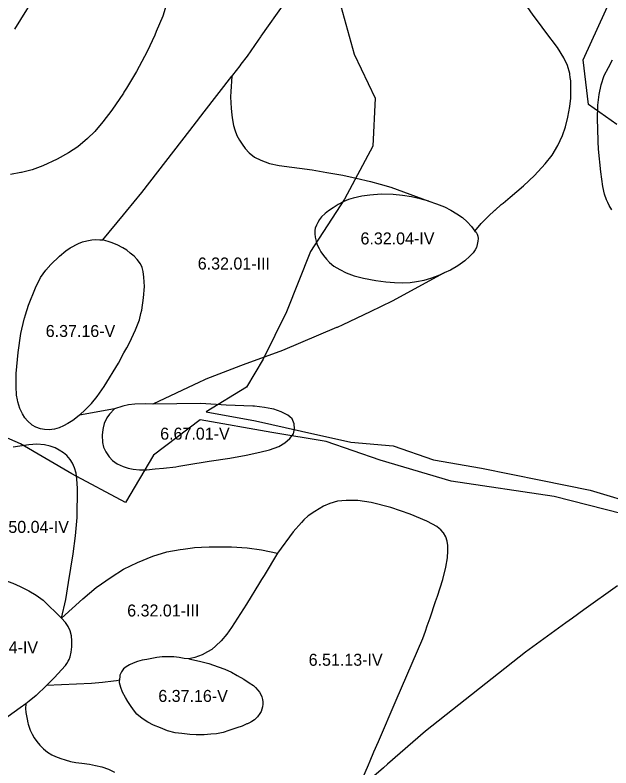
# Model space of a CAD drawing. Extents: x -555156 to -540209, y -1046851 to -1035695.
# Drawn here: x -543996 to -543499, y -1039781 to -1039153 of the extents above; entities that cross this region are included whole.
import ezdxf

# ---------------------------------------------------------------- set-up
doc = ezdxf.new("R2010")
doc.units = 0
for name, color, linetype in [('Vrstva 27', 7, 'Continuous'), ('Vrstva 28', 7, 'Continuous'), ('Vrstva 29', 7, 'Continuous')]:
    doc.layers.add(name, color=color, linetype=linetype)

msp = doc.modelspace()

# ---------------------------------------------------------------- linework, layer by layer
at = {"layer": 'Vrstva 28'}
for points in [[(-543869.35, -1039142.47), (-543873.01, -1039154.5), (-543875.74, -1039160.87), (-543878.5, -1039167.32), (-543879.8, -1039170.14), (-543886.08, -1039183.79), (-543894.97, -1039200.53), (-543903.32, -1039214.33), (-543905.42, -1039217.79), (-543905.88, -1039218.46), (-543915.62, -1039232.7), (-543923.04, -1039242.44), (-543929.76, -1039250.51), (-543935.89, -1039256.34), (-543943.95, -1039263.22), (-543951.57, -1039268.45), (-543961.13, -1039273.53), (-543973.08, -1039279.06), (-543982.04, -1039282.5), (-543985.24, -1039283.25), (-543991.05, -1039284.61), (-543991.6, -1039284.74), (-544000.11, -1039286.38)], [(-543771.41, -1039143.35), (-543791.13, -1039171), (-543791.65, -1039171.76), (-543793.42, -1039174.37), (-543802.57, -1039187.84), (-543807.8, -1039194.41), (-543808.8, -1039195.72), (-543814.8, -1039203.62), (-543815.42, -1039204.43)], [(-543612.61, -1039333.64), (-543607.39, -1039327.22), (-543601.71, -1039321.54), (-543596.11, -1039316.23), (-543595.88, -1039316.01), (-543590.66, -1039311.37), (-543589.15, -1039310.17), (-543583.19, -1039305.4), (-543572, -1039295.78), (-543563.03, -1039287.27), (-543554.07, -1039277.55), (-543548.25, -1039270.38), (-543543.47, -1039262.31), (-543539.58, -1039253.79), (-543537.19, -1039246.62), (-543535.1, -1039238.69), (-543533.54, -1039229.62), (-543532.65, -1039222.74), (-543532.5, -1039216.16), (-543532.65, -1039208.24), (-543533.05, -1039205.49), (-543533.46, -1039202.66), (-543533.54, -1039202.12), (-543535.48, -1039195.54), (-543538.47, -1039189.11), (-543543.73, -1039180.59), (-543553.4, -1039167.77), (-543559.73, -1039159.41), (-543564.07, -1039153.68), (-543568.98, -1039146.3)], [(-543498.55, -1039315.99), (-543500.51, -1039312.23), (-543501.81, -1039309.67), (-543502.9, -1039307.53), (-543504.44, -1039302.66), (-543505.94, -1039296.34), (-543507.59, -1039284.23), (-543509.53, -1039265.4), (-543509.73, -1039258.78), (-543510.05, -1039248.08), (-543510.28, -1039240.44), (-543510.11, -1039228.65), (-543509.06, -1039219.84), (-543507.27, -1039211.77), (-543504.73, -1039203.99), (-543501.29, -1039197.12), (-543497.86, -1039190.84)], [(-543923.2, -1039340.97), (-543905.93, -1039320.1), (-543903.43, -1039317.08), (-543890.52, -1039301.47), (-543850.45, -1039249.71), (-543847.58, -1039246), (-543838.42, -1039234.17), (-543815.42, -1039204.43)], [(-543815.42, -1039204.43), (-543816.37, -1039217.23), (-543816.45, -1039221.75), (-543816.28, -1039226.79), (-543816.02, -1039231.06), (-543815.51, -1039236.95), (-543814.91, -1039240.88), (-543814.06, -1039245.41), (-543813.04, -1039249.08), (-543811.16, -1039253.95), (-543809.11, -1039257.71), (-543806.72, -1039261.12), (-543804.33, -1039264.62), (-543801.09, -1039268.34), (-543796.56, -1039271.92), (-543791.36, -1039274.4), (-543783.93, -1039277.13), (-543775.91, -1039279.01), (-543748.33, -1039282.41), (-543736.23, -1039284.65), (-543722.79, -1039287.05), (-543711.77, -1039289.54), (-543699.63, -1039292.28), (-543691.81, -1039294.51), (-543682.9, -1039297.06)], [(-543682.9, -1039297.06), (-543651.2, -1039308.7)], [(-543651.2, -1039308.7), (-543658.29, -1039306.66), (-543665.54, -1039305.03), (-543672.97, -1039303.84), (-543680.82, -1039303.15), (-543690.72, -1039302.9), (-543700.28, -1039303.58), (-543706.94, -1039304.52), (-543714.11, -1039306.06), (-543718.21, -1039307.34), (-543721.97, -1039308.97), (-543726.83, -1039311.44), (-543730.93, -1039314.09), (-543734.69, -1039316.65), (-543737.5, -1039318.87), (-543740.57, -1039321.78), (-543742.28, -1039324), (-543743.73, -1039326.3), (-543744.84, -1039328.52), (-543745.95, -1039331), (-543746.29, -1039333.13), (-543746.29, -1039335.78), (-543745.95, -1039338.6), (-543745.18, -1039342.1), (-543744.16, -1039345.01), (-543742.62, -1039348.08), (-543741.09, -1039350.81), (-543739.04, -1039353.89), (-543736.56, -1039356.88), (-543733.83, -1039359.86), (-543730.35, -1039362.79), (-543725.31, -1039365.61), (-543720.19, -1039368.26), (-543713.28, -1039370.82), (-543705.51, -1039372.78), (-543695.44, -1039374.66), (-543686.99, -1039375.94), (-543679.73, -1039376.45), (-543672.99, -1039376.62), (-543666.59, -1039376.45)], [(-543651.2, -1039308.7), (-543644.63, -1039310.84), (-543638.15, -1039313.32), (-543632.68, -1039316.22), (-543627.65, -1039319.29), (-543623.12, -1039322.37), (-543619.11, -1039325.87), (-543615.61, -1039329.8), (-543612.61, -1039333.64)], [(-543612.61, -1039333.64), (-543611.73, -1039334.55), (-543610.75, -1039336.26), (-543610.31, -1039337.72), (-543610.07, -1039339.62), (-543610.16, -1039342.02), (-543610.65, -1039344.65), (-543611.43, -1039347.38), (-543612.36, -1039349.24), (-543614.05, -1039351.75), (-543616.79, -1039354.4), (-543620.97, -1039358.24), (-543627.03, -1039362.51), (-543633, -1039366.1), (-543638.21, -1039368.49)], [(-543963.42, -1039498.58), (-543967.78, -1039499.26), (-543971.62, -1039499.01), (-543975.2, -1039498.41), (-543979.04, -1039497.04), (-543981.94, -1039495.25), (-543985.96, -1039491.83), (-543988.09, -1039489.19), (-543990.22, -1039485.86), (-543992.19, -1039481.5), (-543993.98, -1039476.03), (-543994.31, -1039474.15), (-543995, -1039470.23), (-543995.43, -1039463.14), (-543995.26, -1039452.38), (-543993.79, -1039434.72), (-543991.4, -1039418.88), (-543988.82, -1039407.11), (-543988.71, -1039406.62), (-543988.54, -1039406.09), (-543987.67, -1039403.37), (-543985.12, -1039395.41), (-543979.37, -1039380.82), (-543978.91, -1039379.93), (-543975.89, -1039374.13), (-543974.97, -1039372.37), (-543970.7, -1039366.22), (-543966.52, -1039361.43), (-543959.18, -1039354.35), (-543954.06, -1039350.15), (-543950.35, -1039347.51), (-543943.28, -1039343.9), (-543940.01, -1039342.63), (-543936.5, -1039341.56), (-543932.31, -1039340.88), (-543929.14, -1039340.59), (-543925.58, -1039340.73), (-543923.2, -1039340.97)], [(-543942.43, -1039486.97), (-543937.48, -1039482.44), (-543932.61, -1039477.32), (-543927.74, -1039471.34), (-543922.08, -1039463.18), (-543909.98, -1039443.6), (-543905.42, -1039435.14), (-543903.07, -1039430.79), (-543900.87, -1039426.71), (-543895.71, -1039415.77), (-543892.58, -1039407.55), (-543891.24, -1039402.4), (-543890.48, -1039399.48), (-543889.14, -1039389.16), (-543888.39, -1039379.9), (-543888.78, -1039371.91), (-543889.46, -1039367.39), (-543890.23, -1039363.89), (-543891.76, -1039360.9), (-543894.5, -1039357.31), (-543896.97, -1039354.49), (-543900.21, -1039351.84), (-543903.12, -1039349.54), (-543906.45, -1039347.4), (-543910.97, -1039345.1), (-543916.09, -1039343.05), (-543923.2, -1039340.97)], [(-543638.21, -1039368.49), (-543681.7, -1039391.96), (-543699.92, -1039400.93), (-543722.83, -1039411.66), (-543727.6, -1039413.89), (-543728, -1039414.08), (-543773.2, -1039433.2), (-543805.87, -1039444.97), (-543808.21, -1039445.88), (-543837.19, -1039457.15), (-543838.81, -1039457.78), (-543842.48, -1039459.5), (-543881.41, -1039477.78)], [(-543666.59, -1039376.45), (-543661.3, -1039375.68), (-543654.9, -1039374.4), (-543649.39, -1039372.76), (-543643.33, -1039370.62), (-543638.21, -1039368.49)], [(-543913.33, -1039481.79), (-543917.51, -1039486.21), (-543919.81, -1039489.37), (-543921.86, -1039493.98), (-543922.76, -1039497.59), (-543923.14, -1039499.1), (-543923.74, -1039503.71), (-543923.31, -1039509.69), (-543922.37, -1039513.62), (-543920.58, -1039517.55), (-543917.76, -1039521.73), (-543914.86, -1039524.81), (-543911.1, -1039527.71), (-543906.07, -1039529.85), (-543901.97, -1039531.21), (-543897.87, -1039532.07), (-543892.41, -1039532.58), (-543886.61, -1039532.58), (-543879.27, -1039531.9), (-543872.4, -1039531.17), (-543862.07, -1039529.97), (-543859.62, -1039529.57), (-543852.98, -1039528.5), (-543834.31, -1039525.36), (-543816.98, -1039522.82), (-543803.39, -1039520.28), (-543792.19, -1039517.74), (-543783.97, -1039515.95), (-543776.35, -1039513.26), (-543771.12, -1039510.12), (-543767.09, -1039506.53), (-543763.95, -1039502.5), (-543763.06, -1039498.31), (-543763.36, -1039494.28), (-543765, -1039490.09), (-543767.01, -1039488.48), (-543768.73, -1039487.1), (-543774.41, -1039484.26), (-543780.53, -1039482.02), (-543782.03, -1039481.73), (-543788.15, -1039480.53), (-543796.62, -1039479.66), (-543798.01, -1039479.52), (-543820.23, -1039478.73), (-543841.4, -1039477.43)], [(-543881.41, -1039477.78), (-543887.55, -1039477.7), (-543896.26, -1039477.87), (-543901.72, -1039478.29), (-543906.33, -1039479.49), (-543913.33, -1039481.79)], [(-543841.4, -1039477.43), (-543881.41, -1039477.78)], [(-543913.33, -1039481.79), (-543942.43, -1039486.97)], [(-543942.43, -1039486.97), (-543944.08, -1039488.31), (-543947.97, -1039491.49), (-543952.16, -1039493.88), (-543955.74, -1039496.02), (-543959.41, -1039497.47), (-543963.42, -1039498.58)], [(-543953.85, -1039640.58), (-543951.61, -1039626.54), (-543947.69, -1039602.74), (-543945.9, -1039587.49), (-543944.56, -1039572.25), (-543944.41, -1039562.81), (-543944.33, -1039557.66), (-543944.26, -1039553.05), (-543944.18, -1039548.04), (-543944.7, -1039540.01), (-543945.29, -1039535.4), (-543946.57, -1039530.87), (-543948.28, -1039527.03), (-543950.24, -1039523.87), (-543953.06, -1039520.71), (-543955.96, -1039518.4), (-543959.46, -1039516.1), (-543962.96, -1039514.3), (-543967.06, -1039512.77), (-543971.84, -1039511.83), (-543978.07, -1039511.32), (-543984.9, -1039511.66), (-543997.85, -1039513.61)], [(-543678.31, -1039724.54), (-543656.09, -1039673.28), (-543654.99, -1039670.09), (-543653.92, -1039667), (-543652.46, -1039662.78), (-543650.11, -1039655.96), (-543645.42, -1039642.38), (-543643.88, -1039637.93), (-543639.4, -1039624.03), (-543637.01, -1039613.72), (-543635.63, -1039605.93), (-543635.25, -1039600.06), (-543635.21, -1039599.36), (-543635.21, -1039595.6), (-543635.72, -1039592.18), (-543637, -1039588.34), (-543638.88, -1039585.1), (-543639.19, -1039584.77), (-543641.18, -1039582.62), (-543642.46, -1039581.55), (-543644.34, -1039579.97), (-543647.92, -1039577.84), (-543652.67, -1039575.43), (-543666.56, -1039569.61), (-543682.84, -1039563.93), (-543699.27, -1039559.89), (-543710.33, -1039558.1), (-543720.19, -1039558.1), (-543727.21, -1039558.85), (-543733.63, -1039560.79), (-543738.86, -1039563.03), (-543746.33, -1039567.21), (-543751.7, -1039570.95), (-543755.25, -1039574.41), (-543757.38, -1039576.48), (-543764.25, -1039584.25), (-543777.31, -1039602.08)], [(-543957.44, -1039656.13), (-543939.67, -1039640.19), (-543928.62, -1039630.62), (-543916.22, -1039622.1), (-543905.77, -1039615.53), (-543894.12, -1039609.85), (-543881.42, -1039604.47), (-543869.77, -1039601.03), (-543858.42, -1039598.94), (-543855.98, -1039598.63), (-543848.17, -1039597.65), (-543846.47, -1039597.44), (-543840.65, -1039597.16), (-543834.22, -1039596.85), (-543815.85, -1039596.85), (-543802.55, -1039597.74), (-543790.75, -1039599.24), (-543777.31, -1039602.08)], [(-543777.31, -1039602.08), (-543788.59, -1039620.7), (-543790.6, -1039624.02), (-543792.35, -1039626.92), (-543803.08, -1039644.66), (-543815.62, -1039664.01), (-543819.69, -1039669.62), (-543824.47, -1039675.15), (-543828.66, -1039679.33), (-543832.09, -1039682.32), (-543835.83, -1039684.41), (-543840.31, -1039686.95)], [(-544052.34, -1039612.26), (-544044.67, -1039614.28), (-544035.71, -1039616.37), (-544024.36, -1039619.21), (-544014.95, -1039621.6), (-544005.09, -1039624.59), (-543998.22, -1039627.13), (-543991.94, -1039629.97), (-543984.92, -1039633.56), (-543978.8, -1039637.15), (-543972.97, -1039641.33), (-543957.44, -1039656.13)], [(-543493.68, -1039629.17), (-543521.66, -1039649.33), (-543531.19, -1039656.2), (-543536.67, -1039660.15), (-543570.53, -1039684.55), (-543653.79, -1039750.46), (-543685.64, -1039778.03), (-543689.02, -1039780.95), (-543710.72, -1039799.73)], [(-543957.44, -1039656.13), (-543953.85, -1039640.58)], [(-543970.12, -1039712.44), (-543963.29, -1039705.78), (-543957.66, -1039699.37), (-543954.33, -1039695.79), (-543953.2, -1039694.04), (-543951.96, -1039692.11), (-543951.28, -1039690.64), (-543950.26, -1039688.44), (-543949.4, -1039684.6), (-543948.89, -1039680.24), (-543948.98, -1039675.29), (-543949.32, -1039670.93), (-543950.34, -1039666.92), (-543952.05, -1039663.33), (-543954.18, -1039660), (-543957.44, -1039656.13)], [(-543851.21, -1039690.24), (-543855.24, -1039689.82), (-543859.51, -1039689.14), (-543863.95, -1039688.63), (-543868.55, -1039688.37), (-543873.5, -1039688.46), (-543878.03, -1039689.05), (-543882.3, -1039689.82), (-543886.39, -1039690.59), (-543890.23, -1039691.36), (-543894.07, -1039692.39), (-543897.75, -1039693.75), (-543900.9, -1039695.2), (-543903.46, -1039696.74), (-543905.77, -1039698.53), (-543907.48, -1039700.93), (-543908.76, -1039703.83), (-543908.95, -1039705.31), (-543909.18, -1039707.07), (-543909.16, -1039707.91)], [(-543840.31, -1039686.95), (-543846.43, -1039689.04), (-543851.21, -1039690.24)], [(-543851.21, -1039690.24), (-543842.46, -1039692.11), (-543834.71, -1039694.07), (-543826.9, -1039696.8), (-543821.34, -1039698.85), (-543815.64, -1039701.34), (-543810.91, -1039703.97), (-543805.44, -1039707.14), (-543800.86, -1039710.12), (-543797.46, -1039712.53), (-543795.56, -1039714.1), (-543793.85, -1039716.15), (-543792.48, -1039717.85), (-543791.31, -1039719.95), (-543790.53, -1039721.95), (-543789.95, -1039724.05), (-543789.66, -1039725.95), (-543789.7, -1039728), (-543789.95, -1039730.3), (-543790.29, -1039732.15), (-543790.97, -1039734.01), (-543791.96, -1039735.76), (-543793.92, -1039738.41), (-543795.21, -1039739.65), (-543796.57, -1039740.97), (-543798.77, -1039742.48), (-543799.56, -1039743.02), (-543802.46, -1039744.32), (-543802.8, -1039744.47), (-543806.81, -1039746.18), (-543811.14, -1039747.78), (-543817.89, -1039750), (-543822.75, -1039751.54), (-543828.3, -1039752.65), (-543832.91, -1039753.08), (-543838.46, -1039753.42)], [(-543909.16, -1039707.91), (-543911.55, -1039708.38), (-543914.21, -1039708.91), (-543923.33, -1039709.96), (-543932.59, -1039710.71), (-543970.12, -1039712.44)], [(-543838.46, -1039753.42), (-543845.11, -1039753.42), (-543850.49, -1039753.16), (-543857.15, -1039752.48), (-543862.78, -1039751.88), (-543869.18, -1039750.17), (-543875.07, -1039747.7), (-543880.88, -1039745.39), (-543885.4, -1039743), (-543890.27, -1039740.01), (-543894.62, -1039736.34), (-543897.35, -1039732.75), (-543899.91, -1039728.99), (-543902.22, -1039725.84), (-543904.23, -1039722.53), (-543906.62, -1039717.83), (-543908.07, -1039713.99), (-543909.1, -1039710.23), (-543909.13, -1039709.13), (-543909.16, -1039707.91)], [(-543970.12, -1039712.44), (-543978.57, -1039720.7), (-543984.4, -1039725.48), (-543987.26, -1039727.56)], [(-543987.26, -1039727.56), (-543992.02, -1039731.01), (-544002.07, -1039738.17), (-544003.97, -1039739.53), (-544023.08, -1039752.24)], [(-543987.26, -1039727.56), (-543987.47, -1039731.48), (-543987.21, -1039734.89), (-543986.27, -1039740.53), (-543985.57, -1039743.4), (-543985.25, -1039744.71), (-543983.62, -1039749.67), (-543982.09, -1039753.08), (-543980.21, -1039756.16), (-543978.16, -1039759.15), (-543975.6, -1039762.13), (-543972.61, -1039765.21), (-543969.11, -1039768.07), (-543965.7, -1039770.12), (-543962.46, -1039771.66), (-543958.1, -1039773.28), (-543954.6, -1039774.39), (-543949.91, -1039775.67), (-543945.47, -1039776.52), (-543940.69, -1039777.12)], [(-543710.72, -1039799.73), (-543701.53, -1039778.42), (-543700.17, -1039775.27), (-543696.95, -1039767.8), (-543693.22, -1039759.13), (-543678.31, -1039724.54)], [(-543940.69, -1039777.12), (-543934.16, -1039778.08), (-543929.3, -1039779.02), (-543923.83, -1039780.22), (-543918.29, -1039782.1), (-543913.25, -1039784.57)]]:
    msp.add_lwpolyline(points, dxfattribs=at)
at = {"layer": 'Vrstva 29'}
for points in [[(-543494.297002, -1039244.743003), (-543518.001009, -1039228.173992), (-543522.327, -1039190.788997), (-543503.511997, -1039149.268002), (-543480.035005, -1039096.470007)], [(-543996.447021, -1039165.338989), (-543975.200989, -1039130.426025)], [(-543727.339007, -1039135.783009), (-543713.521994, -1039186.067992), (-543695.836996, -1039222.704993), (-543697.902997, -1039262.785993), (-543721.313994, -1039306.922003), (-543749.787005, -1039350.567996), (-543769.706004, -1039400.906007), (-543789.338993, -1039440.307991), (-543803.342001, -1039463.682998), (-543836.741996, -1039484.163002), (-543795.814, -1039491.690009), (-543757.285996, -1039500.258995), (-543716.275004, -1039509.578997), (-543680.782006, -1039512.501002), (-543647.151995, -1039524.165997), (-543607.187993, -1039531.090003), (-543557.569003, -1039541.240996), (-543516.460998, -1039549.549998), (-543473.994004, -1039562.324995)], [(-543475.52002, -1039572.88501), (-543546.606995, -1039554.794006), (-543632.528015, -1039542.151001), (-543691.642029, -1039524.453003), (-543736.651001, -1039508.882996), (-543782.184998, -1039501.421021), (-543841.979004, -1039490.794983), (-543880.859985, -1039520.432983), (-543904.062012, -1039559.744995), (-543948.799988, -1039536.044006), (-543991.619995, -1039510.997986), (-544034.541992, -1039492.315979)]]:
    msp.add_lwpolyline(points, dxfattribs=at)

# ---------------------------------------------------------------- texts
at = {"layer": 'Vrstva 27'}
for s, p in [('6.32.04-IV', (-543708.107119, -1039344.67)), ('6.32.01-III', (-543843.856548, -1039365.6)), ('6.37.16-V', (-543970.687974, -1039421.85)), ('6.67.01-V', (-543875.211006, -1039507.44)), ('6.50.04-IV', (-544013.037119, -1039585.18)), ('6.32.01-III', (-543902.736548, -1039654.86)), ('6.32.04-IV', (-544038.827119, -1039685.64)), ('6.51.13-IV', (-543751.331758, -1039695.94)), ('6.37.16-V', (-543876.767974, -1039726.09))]:
    msp.add_text(s, height=10, dxfattribs=at).set_placement(p)

doc.saveas('drawing.dxf')
